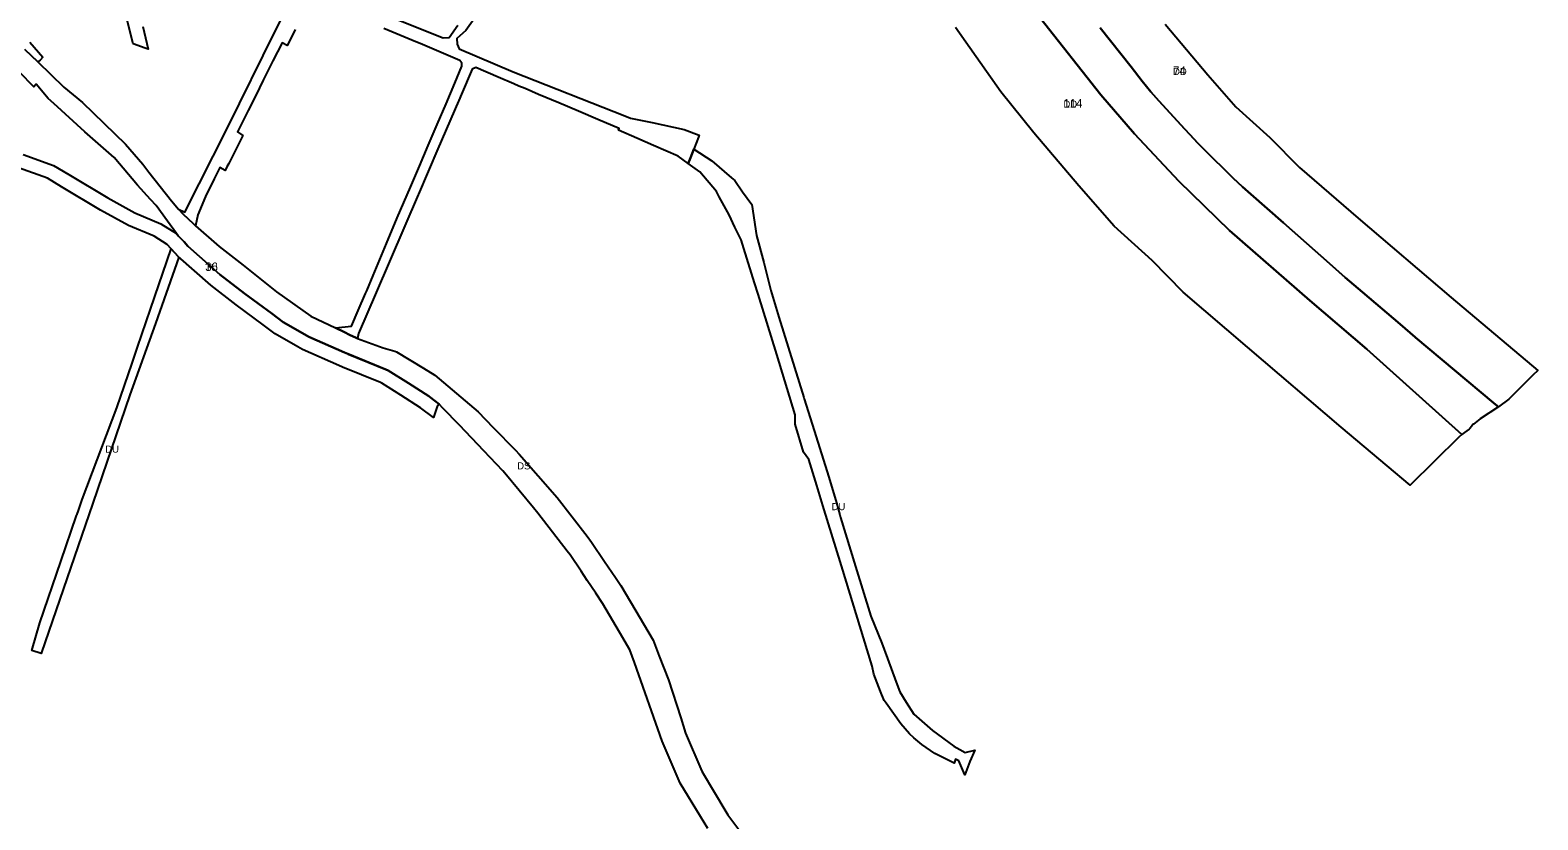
# Model space of a CAD drawing. Extents: x -545758 to -541641, y -1153152 to -1149975.
# Drawn here: x -544135 to -543071, y -1152056 to -1151498 of the extents above; entities that cross this region are included whole.
import ezdxf

# ---------------------------------------------------------------- set-up
doc = ezdxf.new("R2010")
doc.units = 0
for name, color, linetype in [('90310013', 7, 'Continuous'), ('90320013', 7, 'Continuous'), ('90330013', 7, 'Continuous'), ('90330023', 7, 'Continuous'), ('90380023', 7, 'Continuous'), ('90450013', 7, 'Continuous'), ('ID_navrh', 7, 'Continuous')]:
    doc.layers.add(name, color=color, linetype=linetype)

msp = doc.modelspace()

# ---------------------------------------------------------------- linework, layer by layer
at = {"layer": '90310013'}
for points in [[(-543669.066, -1151588.601), (-543666.67, -1151582.48), (-543653.99, -1151590.76), (-543640.19, -1151602.62), (-543637.86, -1151604.63), (-543632.3, -1151612.47), (-543625.86, -1151621.57), (-543622.57, -1151643.32), (-543617.34, -1151662.42), (-543612.37, -1151682.17), (-543606.61, -1151700.87), (-543589.15, -1151757.56), (-543588.85, -1151758.53), (-543581.86, -1151780.91), (-543571.54, -1151813.98), (-543565.94, -1151831.89), (-543563.68, -1151840.49), (-543563.15, -1151842.24), (-543552.58, -1151876.88), (-543541.88, -1151911.96), (-543533.97, -1151930.97), (-543530.01, -1151941.87), (-543523.99, -1151958.44), (-543521.45, -1151965.43), (-543516.9, -1151972.68), (-543511.62, -1151981.09), (-543498.41, -1151992.69), (-543483.3, -1152003.71), (-543479.1, -1152005.99), (-543475.35, -1152008.02), (-543468.38, -1152006.45), (-543471.94, -1152014.51), (-543475.46, -1152023.99), (-543479.81, -1152014.01), (-543482.01, -1152012.9), (-543482.99, -1152015.56), (-543496.73, -1152008.76), (-543505.84, -1152002.5), (-543511.5, -1151997.67), (-543514.55, -1151995.07), (-543520.63, -1151988.01), (-543531.08, -1151973.21), (-543532.44, -1151971.47), (-543534.95, -1151965.03), (-543539.72, -1151952.78), (-543540.86, -1151947.22), (-543562.58, -1151876.34), (-543575.59, -1151833.86), (-543579.9, -1151819.78), (-543585.51, -1151801.47), (-543589.24, -1151796.12), (-543595.23, -1151776.56), (-543595.28, -1151776.41), (-543595.18, -1151769.89), (-543608.23, -1151727.3), (-543621.29, -1151684.66), (-543623.77, -1151676.81), (-543631.4, -1151652.63), (-543633.38, -1151646.34), (-543637.69, -1151637.4), (-543641.79, -1151628.89), (-543648.69, -1151616.13), (-543650.77, -1151612.28), (-543662.32, -1151598.44), (-543670.601, -1151592.521)], [(-544049.74, -1151695.3), (-544035.294, -1151652.8), (-544030.443, -1151658.12), (-544029.924, -1151658.578), (-544046.26, -1151705.45), (-544064.41, -1151755.76), (-544090.59, -1151832.3), (-544126.97, -1151938.18), (-544133.597, -1151936.229), (-544127.82, -1151916.61), (-544113, -1151873.27), (-544101.95, -1151840.94), (-544101.875, -1151840.719), (-544100.474, -1151836.623), (-544098.06, -1151829.56), (-544073.55, -1151765.03), (-544062.77, -1151733.47), (-544058.9, -1151722.15)]]:
    msp.add_lwpolyline(points, close=True, dxfattribs=at)
at = {"layer": '90320013'}
for points in [[(-544138.44, -1151512.18), (-544129.2, -1151520.88), (-544111, -1151538.73), (-544097.69, -1151549.46), (-544067.38, -1151579.03), (-544055.2, -1151593.01), (-544050.91, -1151598.59), (-544035.12, -1151618.93), (-544030.21, -1151624.9), (-544026.53, -1151628.45), (-544019.83, -1151634.91), (-544018.07, -1151636.61), (-544001.52, -1151651.15), (-543984.54, -1151664.4), (-543961.06, -1151683.01), (-543936.67, -1151700.16), (-543919.38, -1151708.54), (-543913, -1151711.64), (-543909.44, -1151713.37), (-543904.84, -1151715.61), (-543903.8, -1151716.11), (-543885.87, -1151722.63), (-543877.54, -1151725.05), (-543876.44, -1151725.37), (-543857.35, -1151737.01), (-543849.25, -1151741.95), (-543818.82, -1151767.88), (-543808.08, -1151778.88), (-543792.5, -1151794.83), (-543789.76, -1151797.63), (-543762.98, -1151828.24), (-543741.95, -1151855.55), (-543738.74, -1151859.72), (-543729.57, -1151873.29), (-543721.82, -1151884.77), (-543718.05, -1151890.35), (-543711.38, -1151901.72), (-543695.44, -1151928.88), (-543691.1, -1151940.05), (-543684.57, -1151956.85), (-543675.92, -1151983.71), (-543672.46, -1151994.45), (-543661.13, -1152021.21), (-543659.46, -1152024.02), (-543653.53, -1152033.97), (-543642.79, -1152052.02), (-543635.03, -1152062.35)], [(-543656.75, -1152061.68), (-543661.89, -1152053.31), (-543676.4, -1152029.69), (-543688.91, -1152000.16), (-543708.6, -1151944.53), (-543711.73, -1151935.7), (-543719.11, -1151923.19), (-543730.91, -1151903.16), (-543735.78, -1151895.71), (-543741.85, -1151886.67), (-543746.14, -1151880.29), (-543753.93, -1151868.68), (-543755.96, -1151866.05), (-543776.57, -1151839.36), (-543779.82, -1151835.4), (-543799.9, -1151810.96), (-543801.27, -1151809.3), (-543814.68, -1151795.28), (-543831.95, -1151777.22), (-543843.58, -1151765.07), (-543846.21, -1151762.33), (-543852.41, -1151757.55), (-543853.63, -1151756.65), (-543867.82, -1151747.63), (-543882.12, -1151738.54), (-543883.89, -1151737.82), (-543883.89, -1151737.82), (-543910.67, -1151726.94), (-543913.02, -1151725.92), (-543938.15, -1151714.94), (-543941.03, -1151713.28), (-543956.3, -1151704.44), (-543964.31, -1151698.48), (-543983.48, -1151684.21), (-544000.97, -1151670.79), (-544023.42, -1151650.98), (-544026.21, -1151647.92), (-544030.25, -1151643.49), (-544031.62, -1151641.99), (-544037.81, -1151633.31), (-544045.76, -1151622.18), (-544049.77, -1151617.91), (-544059.11, -1151607.82), (-544075.47, -1151588.38), (-544096.05, -1151570.2), (-544118.11, -1151550.18), (-544122.04, -1151546.61), (-544130.43, -1151536.56), (-544132.12, -1151538.41), (-544142.25, -1151528.08)]]:
    msp.add_lwpolyline(points, dxfattribs=at)
at = {"layer": '90330013'}
msp.add_lwpolyline([(-543380.16, -1151496.84), (-543358.33, -1151524.47), (-543350.42, -1151534.47), (-543344.41, -1151542.05), (-543338.64, -1151548.36), (-543320.46, -1151568.25), (-543316.87, -1151572.17), (-543311.26, -1151578.3), (-543304.19, -1151585.24), (-543289.4, -1151599.75), (-543286.22, -1151602.87), (-543279.62, -1151608.92), (-543273.77, -1151614.1), (-543250.73, -1151634.54), (-543218.4, -1151663.21), (-543207.39, -1151672.98), (-543195.12, -1151683.41), (-543168.57, -1151706), (-543157.86, -1151715.12), (-543157.6, -1151715.34), (-543102.65, -1151761.47), (-543102.39, -1151761.68), (-543099.2, -1151764.35), (-543112.08, -1151772.78), (-543113.27, -1151773.68), (-543116.9, -1151776.44), (-543117.19, -1151776.78), (-543118.26, -1151778.06), (-543119.5, -1151779.55), (-543119.82, -1151779.93), (-543123.16, -1151782.47), (-543125, -1151783.87), (-543192.1, -1151723.45), (-543232.12, -1151689.27), (-543288.94, -1151639.78), (-543324.56, -1151605.12), (-543355.96, -1151571.72), (-543379.7, -1151544.02), (-543422.57, -1151489.55)], dxfattribs=at)
at = {"layer": '90330023'}
for points in [[(-543422.57, -1151489.55), (-543379.7, -1151544.02), (-543355.96, -1151571.72), (-543324.56, -1151605.12), (-543288.94, -1151639.78), (-543232.12, -1151689.27), (-543192.1, -1151723.45), (-543125, -1151783.87), (-543127.26, -1151785.58), (-543161.495, -1151819.584), (-543210.091, -1151778.565), (-543276.293, -1151722.188), (-543321.453, -1151683.278), (-543343.49, -1151660.985), (-543370.121, -1151636.856), (-543395.205, -1151608.327), (-543426.787, -1151570.854), (-543450.213, -1151542.021), (-543482.123, -1151496.531)], [(-543334.333, -1151494.346), (-543304.255, -1151530.033), (-543284.499, -1151552.504), (-543260.47, -1151574.275), (-543239.487, -1151595.502), (-543198.227, -1151631.052), (-543132.489, -1151687.034), (-543071.432, -1151738.571), (-543074.97, -1151742.01), (-543091.89, -1151758.92), (-543099.2, -1151764.35), (-543102.39, -1151761.68), (-543102.65, -1151761.47), (-543157.6, -1151715.34), (-543157.86, -1151715.12), (-543168.57, -1151706), (-543195.12, -1151683.41), (-543207.39, -1151672.98), (-543218.4, -1151663.21), (-543250.73, -1151634.54), (-543273.77, -1151614.1), (-543279.62, -1151608.92), (-543286.22, -1151602.87), (-543289.4, -1151599.75), (-543304.19, -1151585.24), (-543311.26, -1151578.3), (-543316.87, -1151572.17), (-543320.46, -1151568.25), (-543338.64, -1151548.36), (-543344.41, -1151542.05), (-543350.42, -1151534.47), (-543358.33, -1151524.47), (-543380.16, -1151496.84)]]:
    msp.add_lwpolyline(points, dxfattribs=at)
at = {"layer": '90380023'}
msp.add_lwpolyline([(-544139.74, -1151586.23), (-544118.3, -1151593.88), (-544107.46, -1151600.39), (-544080.04, -1151616.83), (-544060.91, -1151627.39), (-544042.66, -1151635.02), (-544031.62, -1151641.99), (-544030.25, -1151643.49), (-544026.21, -1151647.92), (-544023.42, -1151650.98), (-544000.97, -1151670.79), (-543983.48, -1151684.21), (-543964.31, -1151698.48), (-543956.3, -1151704.44), (-543941.03, -1151713.28), (-543938.15, -1151714.94), (-543913.02, -1151725.92), (-543910.669, -1151726.94), (-543910.524, -1151726.999), (-543883.89, -1151737.82), (-543882.121, -1151738.539), (-543867.82, -1151747.63), (-543853.63, -1151756.65), (-543852.41, -1151757.55), (-543846.21, -1151762.33), (-543847.78, -1151763.96), (-543850.356, -1151771.75), (-543859.362, -1151764.855), (-543873.185, -1151756.069), (-543886.723, -1151747.463), (-543887.656, -1151747.084), (-543914.543, -1151736.16), (-543917.013, -1151735.088), (-543942.663, -1151723.881), (-543946.032, -1151721.939), (-543961.808, -1151712.806), (-543970.28, -1151706.502), (-543989.51, -1151692.188), (-544007.329, -1151678.515), (-544030.443, -1151658.12), (-544035.294, -1151652.8), (-544038.099, -1151649.726), (-544047.29, -1151643.923), (-544065.268, -1151636.407), (-544085.029, -1151625.498), (-544112.605, -1151608.965), (-544122.596, -1151602.964), (-544142.902, -1151595.719)], dxfattribs=at)
at = {"layer": '90450013'}
for points in [[(-544055.23, -1151495.99), (-544051.57, -1151511.96), (-544054.195, -1151511.034), (-544058.828, -1151509.401), (-544062.12, -1151508.24), (-544072.41, -1151466.98)], [(-543947.76, -1151497.92), (-543948.81, -1151500.05), (-543953.35, -1151509.25), (-543957.09, -1151507.39), (-543963.55, -1151520.17), (-543970.31, -1151533.73), (-543975.66, -1151544.55), (-543980.96, -1151555.15), (-543988.48, -1151570.24), (-543984.84, -1151572.83), (-543986.67, -1151576.49), (-543990.66, -1151584.5), (-543994.68, -1151592.56), (-543995.93, -1151594.98), (-543997.18, -1151597.39), (-544001.02, -1151595.38), (-544004.96, -1151603.39), (-544011.13, -1151615.89), (-544016.54, -1151628.79), (-544018.07, -1151636.61), (-544019.83, -1151634.91), (-544026.53, -1151628.45), (-544030.21, -1151624.9), (-544025.68, -1151626.95), (-543995.62, -1151567.47), (-543961.96, -1151499.28), (-543956.79, -1151488.97)], [(-543816.4, -1151483.15), (-543827.34, -1151498.65), (-543833.76, -1151504.49), (-543833.67, -1151508.46), (-543832.04, -1151511.64), (-543794.09, -1151527.78), (-543715.42, -1151558.92), (-543711.37, -1151560.52), (-543696.06, -1151563.74), (-543673.57, -1151568.46), (-543662.797, -1151572.534), (-543663.367, -1151574.044), (-543666.67, -1151582.48), (-543669.066, -1151588.601), (-543670.601, -1151592.521), (-543677.64, -1151587.49), (-543695.14, -1151579.76), (-543706.77, -1151574.74), (-543719.77, -1151569.13), (-543719.24, -1151567.9), (-543734.26, -1151561.53), (-543748.02, -1151555.68), (-543761.76, -1151549.71), (-543776.15, -1151543.81), (-543785.66, -1151539.71), (-543789.97, -1151537.93), (-543793.6, -1151536.39), (-543804.63, -1151531.64), (-543820.51, -1151524.74), (-543823.09, -1151525.92), (-543830.51, -1151543.53), (-543832.48, -1151548.12), (-543832.707, -1151548.649), (-543847.145, -1151582.268), (-543860.842, -1151614.164), (-543861.092, -1151614.746), (-543890.633, -1151683.536), (-543903.08, -1151712.52), (-543903.8, -1151716.11), (-543904.84, -1151715.61), (-543909.44, -1151713.37), (-543913, -1151711.64), (-543919.38, -1151708.54), (-543908.17, -1151707.27), (-543903.338, -1151696.225), (-543898.107, -1151684.217), (-543897.32, -1151682.41), (-543892.75, -1151671.54), (-543883.36, -1151649.07), (-543875.82, -1151630.97), (-543866.54, -1151609.28), (-543860.24, -1151594.56), (-543853.96, -1151579.84), (-543847.67, -1151565.16), (-543841.38, -1151550.49), (-543835.21, -1151535.82), (-543830.21, -1151524.01), (-543830.36, -1151521.75), (-543831.79, -1151519.89), (-543858.06, -1151508.67), (-543865.54, -1151505.52), (-543885.28, -1151497.22)], [(-543874.59, -1151491.33), (-543843.54, -1151503.88), (-543839.26, -1151503.64), (-543833.07, -1151494.98)], [(-544134.86, -1151507.04), (-544125.68, -1151517.57), (-544127.71, -1151519.63), (-544129.2, -1151520.88), (-544138.44, -1151512.18)]]:
    msp.add_lwpolyline(points, dxfattribs=at)

# ---------------------------------------------------------------- texts
at = {"layer": '90310013'}
for p in [(-544081.76, -1151796.566), (-543569.491, -1151837.155)]:
    msp.add_text('DU', height=5, rotation=360, dxfattribs=at).set_placement(p)
at = {"layer": '90320013'}
msp.add_text('DS', height=5, rotation=0, dxfattribs=at).set_placement((-543791.234, -1151808.4))
at = {"layer": '90330023'}
for rotation, p in [(0, (-543328.706, -1151530.125)), (360, (-543405.991, -1151553.072))]:
    msp.add_text('DD', height=5, rotation=rotation, dxfattribs=at).set_placement(p)
at = {"layer": '90380023'}
msp.add_text('TU', height=5, rotation=0, dxfattribs=at).set_placement((-544011.23, -1151668.405))
at = {"layer": 'ID_navrh'}
for s, p in [('74', (-543328.706, -1151530.125)), ('114', (-543405.991, -1151553.072)), ('36', (-544011.23, -1151668.405))]:
    msp.add_text(s, height=6, rotation=0, dxfattribs=at).set_placement(p)

doc.saveas('drawing.dxf')
